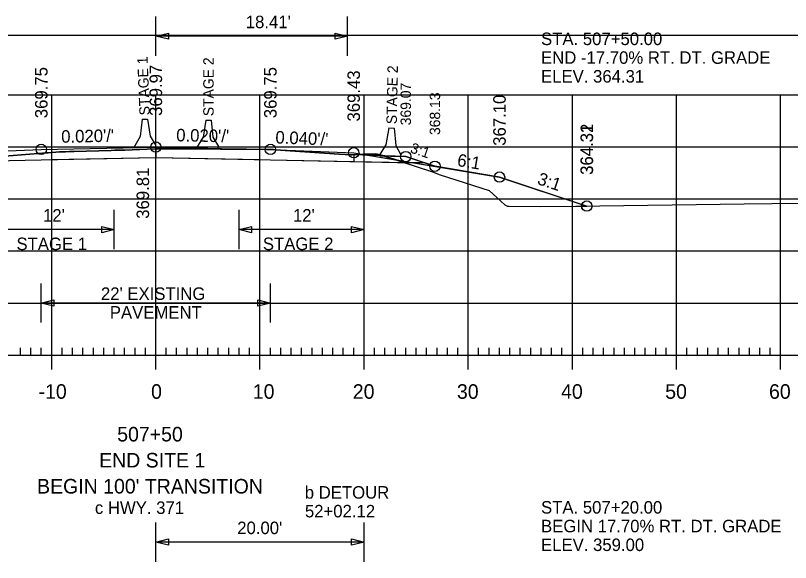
# Model space of a CAD drawing. Extents: x 1368910 to 1369601, y 380116 to 380950.
# Drawn here: x 1369066.8 to 1369141.2, y 380577.8 to 380630.4 of the extents above; entities that cross this region are included whole.
import ezdxf

# ---------------------------------------------------------------- set-up
doc = ezdxf.new("R2010")
doc.units = 0
for name, color, linetype in [('_STAGE 1 CUT', 7, 'Continuous'), ('_STAGE 1 FILL', 7, 'Continuous'), ('_STAGE 2 CUT', 7, 'Continuous'), ('_STAGE 3 CUT', 7, 'Continuous'), ('Notes', 7, 'Continuous'), ('R_Alt Surface', 7, 'Continuous'), ('R_Axis', 7, 'Continuous'), ('R_Axis Annot', 7, 'Continuous'), ('R_CONC BARRIER', 7, 'Continuous'), ('R_Detour Surface', 7, 'Continuous'), ('R_Exist Surface', 7, 'Continuous'), ('R_Fin Surface', 7, 'Continuous'), ('R_Grid', 7, 'Continuous'), ('R_No Plot', 7, 'Continuous'), ('R_ROW Annot', 7, 'Continuous'), ('R_Xsect Elev', 7, 'Continuous'), ('R_Xsect Elev Detour', 7, 'Continuous'), ('R_Xsect Slope', 7, 'Continuous')]:
    doc.layers.add(name, color=color, linetype=linetype)

msp = doc.modelspace()

# ---------------------------------------------------------------- linework, layer by layer
at = {"layer": '_STAGE 1 CUT'}
msp.add_line((1369080.244, 380617.567), (1369080.244, 380616.734), dxfattribs=at)
for points in [[(1369088.944, 380617.526), (1369088.511, 380617.54), (1369087.933, 380617.535), (1369087.039, 380617.524), (1369086.461, 380617.535), (1369084.801, 380617.565), (1369084.294, 380617.553), (1369081.746, 380617.56), (1369080.439, 380617.569), (1369080.294, 380617.569), (1369080.244, 380617.567)], [(1369104.057, 380616.257), (1369103.215, 380616.532), (1369102.005, 380616.926), (1369101.382, 380617.095), (1369100.151, 380617.042), (1369099.089, 380616.997), (1369098.954, 380616.996), (1369097.85, 380617.064), (1369091.743, 380617.473), (1369091.533, 380617.489), (1369091.44, 380617.495), (1369090.864, 380617.497), (1369090.244, 380617.506), (1369088.944, 380617.526)], [(1369080.244, 380616.734), (1369090.244, 380616.534), (1369091.244, 380616.514), (1369104.057, 380616.257)]]:
    msp.add_lwpolyline(points, dxfattribs=at)
at = {"layer": '_STAGE 1 FILL'}
for p, q in [((1369104.971, 380616.239), (1369104.057, 380616.257)), ((1369106.073, 380616.217), (1369104.971, 380616.239)), ((1369107.044, 380615.894), (1369106.073, 380616.217)), ((1369113.244, 380614.86), (1369107.044, 380615.894)), ((1369121.604, 380612.074), (1369113.244, 380614.86))]:
    msp.add_line(p, q, dxfattribs=at)
msp.add_lwpolyline([(1369104.057, 380616.257), (1369106.819, 380615.358), (1369107.548, 380615.065), (1369112.252, 380613.552), (1369113.772, 380612.204), (1369114.026, 380612.063), (1369114.139, 380612.063), (1369117.196, 380612.038), (1369120.575, 380612.06), (1369121.604, 380612.074)], dxfattribs=at)
at = {"layer": '_STAGE 2 CUT'}
msp.add_line((1369080.244, 380616.734), (1369080.244, 380617.567), dxfattribs=at)
for points in [[(1369080.244, 380617.567), (1369079.421, 380617.526), (1369077.258, 380617.442), (1369076.309, 380617.426), (1369075.944, 380617.405), (1369072.391, 380617.319), (1369071.951, 380617.311), (1369071.585, 380617.286), (1369070.999, 380617.278), (1369070.244, 380617.221), (1369069.915, 380617.197), (1369069.742, 380617.177), (1369064.91, 380616.815), (1369062.291, 380616.626), (1369061.588, 380616.361)], [(1369061.588, 380616.361), (1369069.244, 380616.514), (1369070.244, 380616.534), (1369080.244, 380616.734)]]:
    msp.add_lwpolyline(points, dxfattribs=at)
at = {"layer": '_STAGE 3 CUT'}
for p, q in [((1369102.005, 380616.917), (1369100.559, 380616.974)), ((1369102.037, 380616.915), (1369102.005, 380616.917)), ((1369102.245, 380616.907), (1369102.037, 380616.915)), ((1369104.244, 380616.827), (1369102.245, 380616.907))]:
    msp.add_line(p, q, dxfattribs=at)
for points in [[(1369100.559, 380616.974), (1369103.215, 380616.532), (1369104.971, 380616.239), (1369107.044, 380615.894)], [(1369107.044, 380615.894), (1369106.605, 380616.04), (1369104.244, 380616.827)]]:
    msp.add_lwpolyline(points, dxfattribs=at)
at = {"layer": 'R_Alt Surface'}
for points in [[(1369055.516, 380616.239), (1369069.244, 380616.514), (1369080.244, 380616.734), (1369091.244, 380616.514), (1369104.971, 380616.239)], [(1369099.244, 380617.027), (1369099.244, 380616.354), (1369106.073, 380616.217)]]:
    msp.add_lwpolyline(points, dxfattribs=at)
at = {"layer": 'R_Axis'}
for p, q in [((1369070.244, 380596.359), (1369070.244, 380599.159)), ((1369080.244, 380596.359), (1369080.244, 380599.159)), ((1369090.244, 380596.359), (1369090.244, 380599.159)), ((1369100.244, 380596.359), (1369100.244, 380599.159)), ((1369110.244, 380596.359), (1369110.244, 380599.159)), ((1369120.244, 380596.359), (1369120.244, 380599.159)), ((1369130.244, 380596.359), (1369130.244, 380599.159)), ((1369140.244, 380596.359), (1369140.244, 380599.159)), ((1369067.244, 380597.759), (1369067.244, 380598.459)), ((1369068.244, 380597.759), (1369068.244, 380598.459)), ((1369069.244, 380597.759), (1369069.244, 380598.459)), ((1369071.244, 380597.759), (1369071.244, 380598.459)), ((1369072.244, 380597.759), (1369072.244, 380598.459)), ((1369073.244, 380597.759), (1369073.244, 380598.459)), ((1369074.244, 380597.759), (1369074.244, 380598.459)), ((1369075.244, 380597.759), (1369075.244, 380598.459)), ((1369076.244, 380597.759), (1369076.244, 380598.459)), ((1369077.244, 380597.759), (1369077.244, 380598.459)), ((1369078.244, 380597.759), (1369078.244, 380598.459)), ((1369079.244, 380597.759), (1369079.244, 380598.459)), ((1369081.244, 380597.759), (1369081.244, 380598.459)), ((1369082.244, 380597.759), (1369082.244, 380598.459)), ((1369083.244, 380597.759), (1369083.244, 380598.459)), ((1369084.244, 380597.759), (1369084.244, 380598.459)), ((1369085.244, 380597.759), (1369085.244, 380598.459)), ((1369086.244, 380597.759), (1369086.244, 380598.459)), ((1369087.244, 380597.759), (1369087.244, 380598.459)), ((1369088.244, 380597.759), (1369088.244, 380598.459)), ((1369089.244, 380597.759), (1369089.244, 380598.459)), ((1369091.244, 380597.759), (1369091.244, 380598.459)), ((1369092.244, 380597.759), (1369092.244, 380598.459)), ((1369093.244, 380597.759), (1369093.244, 380598.459)), ((1369094.244, 380597.759), (1369094.244, 380598.459)), ((1369095.244, 380597.759), (1369095.244, 380598.459)), ((1369096.244, 380597.759), (1369096.244, 380598.459)), ((1369097.244, 380597.759), (1369097.244, 380598.459)), ((1369098.244, 380597.759), (1369098.244, 380598.459)), ((1369099.244, 380597.759), (1369099.244, 380598.459)), ((1369101.244, 380597.759), (1369101.244, 380598.459)), ((1369102.244, 380597.759), (1369102.244, 380598.459)), ((1369103.244, 380597.759), (1369103.244, 380598.459)), ((1369104.244, 380597.759), (1369104.244, 380598.459)), ((1369105.244, 380597.759), (1369105.244, 380598.459)), ((1369106.244, 380597.759), (1369106.244, 380598.459)), ((1369107.244, 380597.759), (1369107.244, 380598.459)), ((1369108.244, 380597.759), (1369108.244, 380598.459)), ((1369109.244, 380597.759), (1369109.244, 380598.459)), ((1369111.244, 380597.759), (1369111.244, 380598.459)), ((1369112.244, 380597.759), (1369112.244, 380598.459)), ((1369113.244, 380597.759), (1369113.244, 380598.459)), ((1369114.244, 380597.759), (1369114.244, 380598.459)), ((1369115.244, 380597.759), (1369115.244, 380598.459)), ((1369116.244, 380597.759), (1369116.244, 380598.459)), ((1369117.244, 380597.759), (1369117.244, 380598.459)), ((1369118.244, 380597.759), (1369118.244, 380598.459)), ((1369119.244, 380597.759), (1369119.244, 380598.459)), ((1369121.244, 380597.759), (1369121.244, 380598.459)), ((1369122.244, 380597.759), (1369122.244, 380598.459)), ((1369123.244, 380597.759), (1369123.244, 380598.459)), ((1369124.244, 380597.759), (1369124.244, 380598.459)), ((1369125.244, 380597.759), (1369125.244, 380598.459)), ((1369126.244, 380597.759), (1369126.244, 380598.459)), ((1369127.244, 380597.759), (1369127.244, 380598.459)), ((1369128.244, 380597.759), (1369128.244, 380598.459)), ((1369129.244, 380597.759), (1369129.244, 380598.459)), ((1369131.244, 380597.759), (1369131.244, 380598.459)), ((1369132.244, 380597.759), (1369132.244, 380598.459)), ((1369133.244, 380597.759), (1369133.244, 380598.459)), ((1369134.244, 380597.759), (1369134.244, 380598.459)), ((1369135.244, 380597.759), (1369135.244, 380598.459)), ((1369136.244, 380597.759), (1369136.244, 380598.459)), ((1369137.244, 380597.759), (1369137.244, 380598.459)), ((1369138.244, 380597.759), (1369138.244, 380598.459)), ((1369139.244, 380597.759), (1369139.244, 380598.459)), ((1368940.244, 380597.759), (1369220.244, 380597.759))]:
    msp.add_line(p, q, dxfattribs=at)
at = {"layer": 'R_CONC BARRIER'}
for p, q in [((1369078.94, 380620.408), (1369079.44, 380620.418)), ((1369085.047, 380620.338), (1369085.547, 380620.328)), ((1369102.625, 380619.575), (1369103.124, 380619.555)), ((1369078.244, 380617.694), (1369078.241, 380617.86)), ((1369078.244, 380617.694), (1369080.244, 380617.734)), ((1369080.244, 380617.734), (1369080.24, 380617.9)), ((1369084.244, 380617.654), (1369084.247, 380617.82)), ((1369084.244, 380617.654), (1369086.243, 380617.614)), ((1369086.243, 380617.614), (1369086.247, 380617.78)), ((1369101.767, 380616.907), (1369101.774, 380617.073)), ((1369101.767, 380616.907), (1369103.766, 380616.827)), ((1369103.766, 380616.827), (1369103.772, 380616.993))]:
    msp.add_line(p, q, dxfattribs=at)
for points in [[(1369078.94, 380620.408), (1369078.754, 380618.761), (1369078.241, 380617.86)], [(1369079.44, 380620.418), (1369079.691, 380618.78), (1369080.24, 380617.9)], [(1369085.047, 380620.338), (1369084.796, 380618.7), (1369084.247, 380617.82)], [(1369085.547, 380620.328), (1369085.733, 380618.681), (1369086.247, 380617.78)], [(1369102.625, 380619.575), (1369102.34, 380617.942), (1369101.774, 380617.073)], [(1369103.124, 380619.555), (1369103.277, 380617.905), (1369103.772, 380616.993)]]:
    msp.add_lwpolyline(points, dxfattribs=at)
at = {"layer": 'R_Detour Surface'}
msp.add_lwpolyline([(1369099.244, 380617.027), (1369104.244, 380616.827), (1369106.073, 380616.217), (1369107.044, 380615.894)], dxfattribs=at)
at = {"layer": 'R_Exist Surface'}
msp.add_lwpolyline([(1369064.91, 380616.815), (1369069.742, 380617.177), (1369069.915, 380617.197), (1369070.999, 380617.278), (1369071.585, 380617.286), (1369071.951, 380617.311), (1369072.391, 380617.319), (1369075.944, 380617.405), (1369076.309, 380617.426), (1369077.258, 380617.442), (1369079.421, 380617.526), (1369080.294, 380617.569), (1369080.439, 380617.569), (1369081.746, 380617.56), (1369084.294, 380617.553), (1369084.801, 380617.565), (1369086.461, 380617.535), (1369087.039, 380617.524), (1369087.933, 380617.535), (1369088.511, 380617.54), (1369088.944, 380617.526), (1369090.864, 380617.497), (1369091.44, 380617.495), (1369091.533, 380617.489), (1369091.743, 380617.473), (1369097.85, 380617.064), (1369098.954, 380616.996), (1369099.089, 380616.997), (1369101.382, 380617.095), (1369102.005, 380616.926), (1369106.819, 380615.358), (1369107.548, 380615.065), (1369112.252, 380613.552), (1369113.772, 380612.204), (1369114.026, 380612.063), (1369114.139, 380612.063), (1369117.196, 380612.038), (1369120.575, 380612.06), (1369136.75, 380612.274), (1369155.592, 380612.501)], dxfattribs=at)
at = {"layer": 'R_Fin Surface'}
msp.add_lwpolyline([(1369028.737, 380612.773), (1369032.859, 380611.399), (1369036.859, 380611.399), (1369047.244, 380614.86), (1369055.516, 380616.239), (1369061.244, 380617.194), (1369069.244, 380617.514), (1369080.244, 380617.734), (1369091.244, 380617.514), (1369099.244, 380617.194), (1369104.971, 380616.239), (1369113.244, 380614.86), (1369121.618, 380612.069), (1369121.634, 380612.074)], dxfattribs=at)
at = {"layer": 'R_Grid'}
for p, q in [((1368940.244, 380622.759), (1369220.244, 380622.759)), ((1369070.244, 380597.759), (1369070.244, 380622.759)), ((1369080.244, 380597.759), (1369080.244, 380622.759)), ((1369090.244, 380597.759), (1369090.244, 380622.759)), ((1369100.244, 380597.759), (1369100.244, 380622.759)), ((1369110.244, 380597.759), (1369110.244, 380622.759)), ((1369120.244, 380597.759), (1369120.244, 380622.759)), ((1369130.244, 380597.759), (1369130.244, 380622.759)), ((1369140.244, 380597.759), (1369140.244, 380622.759)), ((1368940.244, 380617.759), (1369220.244, 380617.759)), ((1368940.244, 380612.759), (1369220.244, 380612.759)), ((1368940.244, 380607.759), (1369220.244, 380607.759)), ((1368940.244, 380602.759), (1369220.244, 380602.759)), ((1368940.244, 380597.759), (1369220.244, 380597.759))]:
    msp.add_line(p, q, dxfattribs=at)
at = {"layer": 'R_No Plot'}
msp.add_lwpolyline([(1368924.244, 380628.489), (1369236.424, 380628.489), (1369236.424, 380529.759), (1368924.244, 380529.759)], close=True, dxfattribs=at)
for centre in [(1369069.244, 380617.514), (1369080.244, 380617.734), (1369091.244, 380617.514), (1369099.244, 380617.194), (1369104.244, 380616.827), (1369107.044, 380615.894), (1369113.244, 380614.86), (1369113.244, 380614.86), (1369121.618, 380612.069), (1369121.618, 380612.069), (1369121.634, 380612.074)]:
    msp.add_circle(centre, 0.5, dxfattribs=at)
at = {"layer": 'R_ROW Annot'}
for p, q in [((1369080.244, 380626.505), (1369080.244, 380630.273)), ((1369098.655, 380626.505), (1369098.655, 380630.273)), ((1369098.655, 380628.389), (1369080.244, 380628.389)), ((1369076.244, 380607.926), (1369076.244, 380611.695)), ((1369088.244, 380607.926), (1369088.244, 380611.695)), ((1369100.244, 380607.926), (1369100.244, 380611.695)), ((1369076.244, 380609.811), (1369064.244, 380609.811)), ((1369100.244, 380609.811), (1369088.244, 380609.811)), ((1369069.244, 380600.875), (1369069.244, 380604.643)), ((1369091.244, 380600.875), (1369091.244, 380604.643)), ((1369091.244, 380602.759), (1369069.244, 380602.759)), ((1369080.244, 380577.907), (1369080.244, 380581.676)), ((1369100.244, 380577.907), (1369100.244, 380581.676)), ((1369100.244, 380579.791), (1369080.244, 380579.791))]:
    msp.add_line(p, q, dxfattribs=at)
for points in [[(1369081.444, 380628.089), (1369080.244, 380628.389), (1369081.444, 380628.689)], [(1369097.455, 380628.689), (1369098.655, 380628.389), (1369097.455, 380628.089)], [(1369075.044, 380610.111), (1369076.244, 380609.811), (1369075.044, 380609.511)], [(1369089.444, 380609.511), (1369088.244, 380609.811), (1369089.444, 380610.111)], [(1369099.044, 380610.111), (1369100.244, 380609.811), (1369099.044, 380609.511)], [(1369070.444, 380602.459), (1369069.244, 380602.759), (1369070.444, 380603.059)], [(1369090.044, 380603.059), (1369091.244, 380602.759), (1369090.044, 380602.459)], [(1369081.444, 380579.491), (1369080.244, 380579.791), (1369081.444, 380580.091)], [(1369099.044, 380580.091), (1369100.244, 380579.791), (1369099.044, 380579.491)]]:
    msp.add_lwpolyline(points, close=True, dxfattribs=at)

# ---------------------------------------------------------------- texts
at = {"layer": 'Notes'}
for s, p in [('STA. 507+50.00', (1369117.234, 380627.535)), ('END -17.70% RT. DT. GRADE', (1369117.234, 380625.735)), ('ELEV. 364.31', (1369117.234, 380623.935)), ('b DETOUR', (1369094.545, 380583.968)), ('STA. 507+20.00', (1369117.234, 380582.535)), ('c HWY. 371', (1369074.394, 380582.496)), ('52+02.12', (1369094.561, 380582.168)), ('BEGIN 17.70% RT. DT. GRADE', (1369117.234, 380580.735)), ('ELEV. 359.00', (1369117.234, 380578.935))]:
    msp.add_text(s, height=1.2, dxfattribs=at).set_placement(p)
at = {"layer": 'R_Axis Annot'}
for s, p in [('-10', (1369068.981, 380593.559)), ('0', (1369079.786, 380593.559)), ('10', (1369089.555, 380593.559)), ('20', (1369099.158, 380593.559)), ('30', (1369109.158, 380593.559)), ('40', (1369119.158, 380593.559)), ('50', (1369129.158, 380593.559)), ('60', (1369139.125, 380593.559)), ('507+50', (1369076.534, 380589.459)), ('END SITE 1', (1369074.798, 380586.959)), ("BEGIN 100' TRANSITION", (1369068.84, 380584.459))]:
    msp.add_text(s, height=1.4, dxfattribs=at).set_placement(p)
at = {"layer": 'R_CONC BARRIER'}
for s, rotation, p in [(' STAGE 1', 92.29153, (1369079.689, 380620.433)), (' STAGE 2', 90, (1369085.797, 380620.333)), (' STAGE 2', 88.85515, (1369103.374, 380619.555))]:
    msp.add_text(s, height=1, rotation=rotation, dxfattribs=at).set_placement(p)
at = {"layer": 'R_ROW Annot'}
for s, p in [("18.41'", (1369088.882, 380629.159)), ("12'", (1369069.412, 380610.58)), ("12'", (1369093.412, 380610.58)), ('STAGE 1', (1369066.861, 380607.841)), ('STAGE 2', (1369090.521, 380607.841)), ("22' EXISTING", (1369074.976, 380603.059)), ('PAVEMENT', (1369075.826, 380601.259)), ("20.00'", (1369088.06, 380580.561))]:
    msp.add_text(s, height=1.2, dxfattribs=at).set_placement(p)
at = {"layer": 'R_Xsect Elev'}
for s, p in [('369.97', (1369080.844, 380620.734)), ('369.75', (1369069.844, 380620.514)), ('369.75', (1369091.844, 380620.514)), ('369.43', (1369099.844, 380620.194)), ('367.10', (1369113.844, 380617.86)), ('364.31', (1369122.218, 380615.069)), ('364.32', (1369122.234, 380615.074)), ('369.81', (1369079.594, 380610.853))]:
    msp.add_text(s, height=1.2, rotation=90, dxfattribs=at).set_placement(p)
at = {"layer": 'R_Xsect Elev Detour'}
for s, p in [('369.07', (1369104.744, 380619.827)), ('368.13', (1369107.544, 380618.894))]:
    msp.add_text(s, height=1, rotation=90, dxfattribs=at).set_placement(p)
at = {"layer": 'R_Xsect Slope'}
for s, height, rotation, p in [("0.020'/'", 1.2, 1.14576, (1369071.17, 380618.152)), ("0.020'/'", 1.2, 358.85424, (1369082.194, 380618.295)), ("0.040'/'", 1.2, 357.70939, (1369091.708, 380618.096)), ('3:1', 1, 341.56507, (1369104.606, 380617.233)), ('6:1', 1.2, 350.53766, (1369109.12, 380615.931)), ('3:1', 1.2, 341.56507, (1369116.8, 380614.202))]:
    msp.add_text(s, height=height, rotation=rotation, dxfattribs=at).set_placement(p)

doc.saveas('drawing.dxf')
